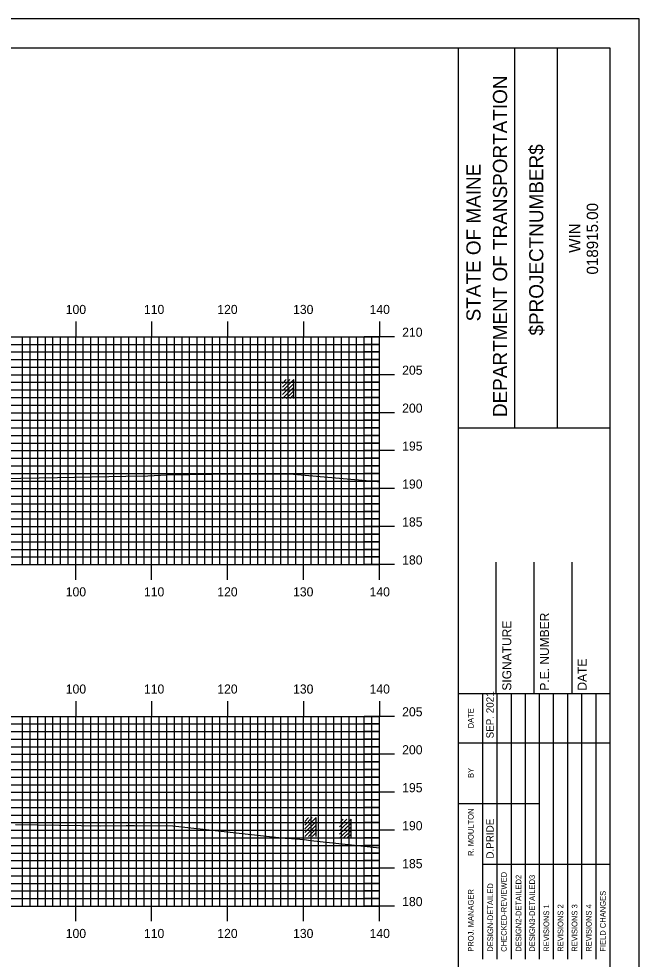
# Model space of a CAD drawing. Extents: x 851300 to 851643, y 366898 to 367118.
# Drawn here: x 851558 to 851639.7, y 366994.5 to 367118.4 of the extents above; entities that cross this region are included whole.
import ezdxf

# ---------------------------------------------------------------- set-up
doc = ezdxf.new("R2010")
doc.units = 0
for name, color, linetype in [('BORDER', 7, 'Continuous'), ('H_V ANNOTATION', 7, 'Continuous'), ('M_Buildings_Attachments', 7, 'Continuous'), ('M_Buildings_Rooftop', 7, 'Continuous'), ('MAJOR', 7, 'Continuous'), ('MINOR', 7, 'Continuous'), ('PLOT BOUNDARY', 7, 'Continuous'), ('S_Roadway_Centerline', 7, 'Continuous')]:
    doc.layers.add(name, color=color, linetype=linetype)

msp = doc.modelspace()

# ---------------------------------------------------------------- linework, layer by layer
at = {"layer": 'BORDER'}
for p, q in [((851615.9, 366904.47), (851615.9, 367114.47)), ((851623.36, 367064.47), (851623.36, 367114.47)), ((851628.95, 367064.47), (851628.95, 367114.47)), ((851615.91, 367064.46), (851635.9, 367064.46)), ((851620.9, 367029.48), (851620.9, 367046.77)), ((851625.9, 367029.48), (851625.9, 367046.77)), ((851630.9, 367029.48), (851630.9, 367046.77)), ((851615.9, 367029.48), (851635.9, 367029.48))]:
    msp.add_line(p, q, dxfattribs=at)
msp.add_lwpolyline([(851315.9, 366904.47), (851635.9, 366904.47), (851635.9, 367114.47), (851315.9, 367114.47)], close=True, dxfattribs=at)
for points in [[(851619.13, 367022.98), (851619.13, 367029.48)], [(851621, 366994.48), (851621, 367029.48)], [(851622.86, 367029.48), (851622.86, 366994.48)], [(851624.73, 366994.48), (851624.73, 367029.48)], [(851626.59, 366994.48), (851626.59, 367029.48)], [(851628.45, 366994.48), (851628.45, 367029.48)], [(851630.32, 366994.48), (851630.32, 367029.48)], [(851632.18, 366994.48), (851632.18, 367029.48)], [(851634.04, 366994.48), (851634.04, 367029.48)], [(851619.14, 366994.48), (851619.14, 367028.07)], [(851615.9, 367022.98), (851635.9, 367022.98)], [(851615.9, 367014.98), (851619.14, 367014.98)], [(851619.13, 367014.98), (851626.59, 367014.98)], [(851619.13, 367006.98), (851635.9, 367006.98)]]:
    msp.add_lwpolyline(points, dxfattribs=at)
at = {"layer": 'M_Buildings_Attachments'}
for p, q in [((851595.66, 367011.65), (851597.17, 367013.16)), ((851595.66, 367012.14), (851596.65, 367013.16)), ((851595.66, 367012.63), (851596.16, 367013.16)), ((851597.17, 367010.63), (851597.17, 367013.16)), ((851600.25, 367011.42), (851601.76, 367012.93)), ((851600.25, 367011.92), (851601.23, 367012.93)), ((851600.25, 367012.41), (851600.74, 367012.93)), ((851601.76, 367010.41), (851601.76, 367012.93)), ((851595.66, 367011.16), (851597.17, 367012.63)), ((851595.66, 367010.63), (851597.17, 367012.14)), ((851596.16, 367010.63), (851597.17, 367011.65)), ((851600.25, 367010.93), (851601.76, 367012.41)), ((851600.25, 367010.41), (851601.76, 367011.92)), ((851596.65, 367010.63), (851597.17, 367011.16)), ((851600.74, 367010.41), (851601.76, 367011.42)), ((851601.23, 367010.41), (851601.76, 367010.93))]:
    msp.add_line(p, q, dxfattribs=at)
at = {"layer": 'M_Buildings_Rooftop'}
for p, q in [((851592.72, 367069.34), (851594.23, 367070.85)), ((851592.72, 367069.83), (851593.71, 367070.85)), ((851592.72, 367070.33), (851593.22, 367070.85)), ((851592.72, 367068.85), (851594.23, 367070.33)), ((851592.72, 367068.32), (851594.23, 367069.83)), ((851594.23, 367068.32), (851594.23, 367070.85)), ((851593.22, 367068.32), (851594.23, 367069.34)), ((851593.71, 367068.32), (851594.23, 367068.85))]:
    msp.add_line(p, q, dxfattribs=at)
at = {"layer": 'MAJOR'}
for p, q in [((851565.5, 367078.48), (851565.5, 367076.47)), ((851575.5, 367078.48), (851575.5, 367076.47)), ((851585.5, 367078.48), (851585.5, 367076.47)), ((851595.5, 367078.48), (851595.5, 367076.47)), ((851605.5, 367078.48), (851605.5, 367076.47)), ((851325.5, 367076.47), (851605.5, 367076.47)), ((851325.5, 367076.47), (851605.5, 367076.47)), ((851565.5, 367046.47), (851565.5, 367076.47)), ((851575.5, 367046.47), (851575.5, 367076.47)), ((851585.5, 367046.47), (851585.5, 367076.47)), ((851595.5, 367046.47), (851595.5, 367076.47)), ((851607.51, 367076.47), (851603.5, 367076.47)), ((851605.5, 367046.47), (851605.5, 367076.47)), ((851605.5, 367046.47), (851605.5, 367076.47)), ((851325.5, 367071.47), (851605.5, 367071.47)), ((851607.51, 367071.47), (851603.5, 367071.47)), ((851325.5, 367066.47), (851605.5, 367066.47)), ((851607.51, 367066.47), (851603.5, 367066.47)), ((851325.5, 367061.47), (851605.5, 367061.47)), ((851607.51, 367061.47), (851603.5, 367061.47)), ((851325.5, 367056.47), (851605.5, 367056.47)), ((851607.51, 367056.47), (851603.5, 367056.47)), ((851325.5, 367051.47), (851605.5, 367051.47)), ((851607.51, 367051.47), (851603.5, 367051.47)), ((851325.5, 367046.47), (851605.5, 367046.47)), ((851325.5, 367046.47), (851605.5, 367046.47)), ((851565.5, 367044.47), (851565.5, 367046.47)), ((851575.5, 367044.47), (851575.5, 367046.47)), ((851585.5, 367044.47), (851585.5, 367046.47)), ((851595.5, 367044.47), (851595.5, 367046.47)), ((851607.51, 367046.47), (851603.5, 367046.47)), ((851605.5, 367044.47), (851605.5, 367046.47)), ((851565.5, 367028.48), (851565.5, 367026.47)), ((851575.5, 367028.48), (851575.5, 367026.47)), ((851585.5, 367028.48), (851585.5, 367026.47)), ((851595.5, 367028.48), (851595.5, 367026.47)), ((851605.5, 367028.48), (851605.5, 367026.47)), ((851325.5, 367026.47), (851605.5, 367026.47)), ((851325.5, 367026.47), (851605.5, 367026.47)), ((851565.5, 367001.47), (851565.5, 367026.47)), ((851575.5, 367001.47), (851575.5, 367026.47)), ((851585.5, 367001.47), (851585.5, 367026.47)), ((851595.5, 367001.47), (851595.5, 367026.47)), ((851607.51, 367026.47), (851603.5, 367026.47)), ((851605.5, 367001.47), (851605.5, 367026.47)), ((851605.5, 367001.47), (851605.5, 367026.47)), ((851325.5, 367021.47), (851605.5, 367021.47)), ((851607.51, 367021.47), (851603.5, 367021.47)), ((851325.5, 367016.47), (851605.5, 367016.47)), ((851607.51, 367016.47), (851603.5, 367016.47)), ((851325.5, 367011.47), (851605.5, 367011.47)), ((851607.51, 367011.47), (851603.5, 367011.47)), ((851325.5, 367006.47), (851605.5, 367006.47)), ((851607.51, 367006.47), (851603.5, 367006.47)), ((851325.5, 367001.47), (851605.5, 367001.47)), ((851325.5, 367001.47), (851605.5, 367001.47)), ((851565.5, 366999.47), (851565.5, 367001.47)), ((851575.5, 366999.47), (851575.5, 367001.47)), ((851585.5, 366999.47), (851585.5, 367001.47)), ((851595.5, 366999.47), (851595.5, 367001.47)), ((851607.51, 367001.47), (851603.5, 367001.47)), ((851605.5, 366999.47), (851605.5, 367001.47))]:
    msp.add_line(p, q, dxfattribs=at)
at = {"layer": 'MINOR'}
for p, q in [((851558.5, 367046.47), (851558.5, 367076.47)), ((851559.5, 367046.47), (851559.5, 367076.47)), ((851560.5, 367046.47), (851560.5, 367076.47)), ((851561.5, 367046.47), (851561.5, 367076.47)), ((851562.5, 367046.47), (851562.5, 367076.47)), ((851563.5, 367046.47), (851563.5, 367076.47)), ((851564.5, 367046.47), (851564.5, 367076.47)), ((851566.5, 367046.47), (851566.5, 367076.47)), ((851567.5, 367046.47), (851567.5, 367076.47)), ((851568.5, 367046.47), (851568.5, 367076.47)), ((851569.5, 367046.47), (851569.5, 367076.47)), ((851570.5, 367046.47), (851570.5, 367076.47)), ((851571.5, 367046.47), (851571.5, 367076.47)), ((851572.5, 367046.47), (851572.5, 367076.47)), ((851573.5, 367046.47), (851573.5, 367076.47)), ((851574.5, 367046.47), (851574.5, 367076.47)), ((851576.5, 367046.47), (851576.5, 367076.47)), ((851577.5, 367046.47), (851577.5, 367076.47)), ((851578.5, 367046.47), (851578.5, 367076.47)), ((851579.5, 367046.47), (851579.5, 367076.47)), ((851580.5, 367046.47), (851580.5, 367076.47)), ((851581.5, 367046.47), (851581.5, 367076.47)), ((851582.5, 367046.47), (851582.5, 367076.47)), ((851583.5, 367046.47), (851583.5, 367076.47)), ((851584.5, 367046.47), (851584.5, 367076.47)), ((851586.5, 367046.47), (851586.5, 367076.47)), ((851587.5, 367046.47), (851587.5, 367076.47)), ((851588.5, 367046.47), (851588.5, 367076.47)), ((851589.5, 367046.47), (851589.5, 367076.47)), ((851590.5, 367046.47), (851590.5, 367076.47)), ((851591.5, 367046.47), (851591.5, 367076.47)), ((851592.5, 367046.47), (851592.5, 367076.47)), ((851593.5, 367046.47), (851593.5, 367076.47)), ((851594.5, 367046.47), (851594.5, 367076.47)), ((851596.5, 367046.47), (851596.5, 367076.47)), ((851597.5, 367046.47), (851597.5, 367076.47)), ((851598.5, 367046.47), (851598.5, 367076.47)), ((851599.5, 367046.47), (851599.5, 367076.47)), ((851600.5, 367046.47), (851600.5, 367076.47)), ((851601.5, 367046.47), (851601.5, 367076.47)), ((851602.5, 367046.47), (851602.5, 367076.47)), ((851603.5, 367046.47), (851603.5, 367076.47)), ((851604.5, 367046.47), (851604.5, 367076.47)), ((851325.5, 367075.47), (851605.5, 367075.47)), ((851605.5, 367075.47), (851603.5, 367075.47)), ((851325.5, 367074.47), (851605.5, 367074.47)), ((851605.5, 367074.47), (851603.5, 367074.47)), ((851325.5, 367073.47), (851605.5, 367073.47)), ((851325.5, 367072.47), (851605.5, 367072.47)), ((851605.5, 367073.47), (851603.5, 367073.47)), ((851605.5, 367072.47), (851603.5, 367072.47)), ((851325.5, 367070.47), (851605.5, 367070.47)), ((851605.5, 367070.47), (851603.5, 367070.47)), ((851325.5, 367069.47), (851605.5, 367069.47)), ((851605.5, 367069.47), (851603.5, 367069.47)), ((851325.5, 367068.47), (851605.5, 367068.47)), ((851325.5, 367067.47), (851605.5, 367067.47)), ((851605.5, 367068.47), (851603.5, 367068.47)), ((851605.5, 367067.47), (851603.5, 367067.47)), ((851325.5, 367065.47), (851605.5, 367065.47)), ((851605.5, 367065.47), (851603.5, 367065.47)), ((851325.5, 367064.47), (851605.5, 367064.47)), ((851605.5, 367064.47), (851603.5, 367064.47)), ((851325.5, 367063.47), (851605.5, 367063.47)), ((851325.5, 367062.47), (851605.5, 367062.47)), ((851605.5, 367063.47), (851603.5, 367063.47)), ((851605.5, 367062.47), (851603.5, 367062.47)), ((851325.5, 367060.47), (851605.5, 367060.47)), ((851605.5, 367060.47), (851603.5, 367060.47)), ((851325.5, 367059.47), (851605.5, 367059.47)), ((851605.5, 367059.47), (851603.5, 367059.47)), ((851325.5, 367058.47), (851605.5, 367058.47)), ((851325.5, 367057.47), (851605.5, 367057.47)), ((851605.5, 367058.47), (851603.5, 367058.47)), ((851605.5, 367057.47), (851603.5, 367057.47)), ((851325.5, 367055.47), (851605.5, 367055.47)), ((851605.5, 367055.47), (851603.5, 367055.47)), ((851325.5, 367054.47), (851605.5, 367054.47)), ((851605.5, 367054.47), (851603.5, 367054.47)), ((851325.5, 367053.47), (851605.5, 367053.47)), ((851605.5, 367053.47), (851603.5, 367053.47)), ((851325.5, 367052.47), (851605.5, 367052.47)), ((851605.5, 367052.47), (851603.5, 367052.47)), ((851325.5, 367050.47), (851605.5, 367050.47)), ((851605.5, 367050.47), (851603.5, 367050.47)), ((851325.5, 367049.47), (851605.5, 367049.47)), ((851605.5, 367049.47), (851603.5, 367049.47)), ((851325.5, 367048.47), (851605.5, 367048.47)), ((851605.5, 367048.47), (851603.5, 367048.47)), ((851325.5, 367047.47), (851605.5, 367047.47)), ((851605.5, 367047.47), (851603.5, 367047.47)), ((851558.5, 367001.47), (851558.5, 367026.47)), ((851559.5, 367001.47), (851559.5, 367026.47)), ((851560.5, 367001.47), (851560.5, 367026.47)), ((851561.5, 367001.47), (851561.5, 367026.47)), ((851562.5, 367001.47), (851562.5, 367026.47)), ((851563.5, 367001.47), (851563.5, 367026.47)), ((851564.5, 367001.47), (851564.5, 367026.47)), ((851566.5, 367001.47), (851566.5, 367026.47)), ((851567.5, 367001.47), (851567.5, 367026.47)), ((851568.5, 367001.47), (851568.5, 367026.47)), ((851569.5, 367001.47), (851569.5, 367026.47)), ((851570.5, 367001.47), (851570.5, 367026.47)), ((851571.5, 367001.47), (851571.5, 367026.47)), ((851572.5, 367001.47), (851572.5, 367026.47)), ((851573.5, 367001.47), (851573.5, 367026.47)), ((851574.5, 367001.47), (851574.5, 367026.47)), ((851576.5, 367001.47), (851576.5, 367026.47)), ((851577.5, 367001.47), (851577.5, 367026.47)), ((851578.5, 367001.47), (851578.5, 367026.47)), ((851579.5, 367001.47), (851579.5, 367026.47)), ((851580.5, 367001.47), (851580.5, 367026.47)), ((851581.5, 367001.47), (851581.5, 367026.47)), ((851582.5, 367001.47), (851582.5, 367026.47)), ((851583.5, 367001.47), (851583.5, 367026.47)), ((851584.5, 367001.47), (851584.5, 367026.47)), ((851586.5, 367001.47), (851586.5, 367026.47)), ((851587.5, 367001.47), (851587.5, 367026.47)), ((851588.5, 367001.47), (851588.5, 367026.47)), ((851589.5, 367001.47), (851589.5, 367026.47)), ((851590.5, 367001.47), (851590.5, 367026.47)), ((851591.5, 367001.47), (851591.5, 367026.47)), ((851592.5, 367001.47), (851592.5, 367026.47)), ((851593.5, 367001.47), (851593.5, 367026.47)), ((851594.5, 367001.47), (851594.5, 367026.47)), ((851596.5, 367001.47), (851596.5, 367026.47)), ((851597.5, 367001.47), (851597.5, 367026.47)), ((851598.5, 367001.47), (851598.5, 367026.47)), ((851599.5, 367001.47), (851599.5, 367026.47)), ((851600.5, 367001.47), (851600.5, 367026.47)), ((851601.5, 367001.47), (851601.5, 367026.47)), ((851602.5, 367001.47), (851602.5, 367026.47)), ((851603.5, 367001.47), (851603.5, 367026.47)), ((851604.5, 367001.47), (851604.5, 367026.47)), ((851325.5, 367025.47), (851605.5, 367025.47)), ((851605.5, 367025.47), (851603.5, 367025.47)), ((851325.5, 367024.47), (851605.5, 367024.47)), ((851605.5, 367024.47), (851603.5, 367024.47)), ((851325.5, 367023.47), (851605.5, 367023.47)), ((851605.5, 367023.47), (851603.5, 367023.47)), ((851325.5, 367022.47), (851605.5, 367022.47)), ((851605.5, 367022.47), (851603.5, 367022.47)), ((851325.5, 367020.47), (851605.5, 367020.47)), ((851605.5, 367020.47), (851603.5, 367020.47)), ((851325.5, 367019.47), (851605.5, 367019.47)), ((851605.5, 367019.47), (851603.5, 367019.47)), ((851325.5, 367018.47), (851605.5, 367018.47)), ((851605.5, 367018.47), (851603.5, 367018.47)), ((851325.5, 367017.47), (851605.5, 367017.47)), ((851605.5, 367017.47), (851603.5, 367017.47)), ((851325.5, 367015.47), (851605.5, 367015.47)), ((851605.5, 367015.47), (851603.5, 367015.47)), ((851325.5, 367014.47), (851605.5, 367014.47)), ((851605.5, 367014.47), (851603.5, 367014.47)), ((851325.5, 367013.47), (851605.5, 367013.47)), ((851605.5, 367013.47), (851603.5, 367013.47)), ((851325.5, 367012.47), (851605.5, 367012.47)), ((851605.5, 367012.47), (851603.5, 367012.47)), ((851325.5, 367010.47), (851605.5, 367010.47)), ((851605.5, 367010.47), (851603.5, 367010.47)), ((851325.5, 367009.47), (851605.5, 367009.47)), ((851605.5, 367009.47), (851603.5, 367009.47)), ((851325.5, 367008.47), (851605.5, 367008.47)), ((851605.5, 367008.47), (851603.5, 367008.47)), ((851325.5, 367007.47), (851605.5, 367007.47)), ((851605.5, 367007.47), (851603.5, 367007.47)), ((851325.5, 367005.47), (851605.5, 367005.47)), ((851605.5, 367005.47), (851603.5, 367005.47)), ((851325.5, 367004.47), (851605.5, 367004.47)), ((851605.5, 367004.47), (851603.5, 367004.47)), ((851325.5, 367003.47), (851605.5, 367003.47)), ((851605.5, 367003.47), (851603.5, 367003.47)), ((851325.5, 367002.47), (851605.5, 367002.47)), ((851605.5, 367002.47), (851603.5, 367002.47))]:
    msp.add_line(p, q, dxfattribs=at)
at = {"layer": 'PLOT BOUNDARY'}
msp.add_lwpolyline([(851299.72, 366898.35), (851639.72, 366898.35), (851639.72, 367118.35), (851299.72, 367118.35)], close=True, dxfattribs=at)
at = {"layer": 'S_Roadway_Centerline'}
for points in [[(851555.87, 367057.79), (851563.08, 367057.93), (851572.09, 367058.12), (851575.02, 367058.17), (851577.51, 367058.27), (851586.54, 367058.42), (851591.01, 367058.41), (851593.71, 367058.43), (851605.25, 367057.4), (851605.5, 367057.41)], [(851557.55, 367012.21), (851566.2, 367012.1), (851568.77, 367012.07), (851572.16, 367012.08), (851573.24, 367012.09), (851578.31, 367012.04), (851591.83, 367010.56), (851593.07, 367010.44), (851593.36, 367010.41), (851595.58, 367010.23), (851596.48, 367010.13), (851605.5, 367009.16)]]:
    msp.add_lwpolyline(points, dxfattribs=at)

# ---------------------------------------------------------------- texts
at = {"layer": 'BORDER'}
for s, height, p in [('DEPARTMENT OF TRANSPORTATION', 1.8635, (851622.32, 367065.89)), ('$PROJECTNUMBER$', 1.8635, (851627.09, 367076.63)), ('STATE OF MAINE', 1.8635, (851618.82, 367078.5)), ('018915.00', 1.491, (851634.3, 367084.67)), ('WIN', 1.491, (851631.98, 367087.53)), ('SIGNATURE', 1.181, (851622.87, 367029.86)), ('P.E. NUMBER', 1.1811, (851627.83, 367029.86)), ('DATE', 1.181, (851632.79, 367029.86)), ('SEP. 2021', 0.969, (851620.55, 367023.57)), ('DATE', 0.743, (851617.91, 367024.89)), ('BY', 0.743, (851617.91, 367018.35)), ('R. MOULTON', 0.745, (851617.91, 367008.08)), ('D.PRIDE', 0.969, (851620.55, 367007.73)), ('CHECKED-REVIEWED', 0.7455, (851622.27, 366995.46)), ('DESIGN2-DETAILED2', 0.7455, (851624.2, 366995.46)), ('DESIGN3-DETAILED3', 0.7455, (851625.99, 366995.46)), ('DESIGN-DETAILED', 0.7455, (851620.48, 366995.46)), ('PROJ. MANAGER', 0.7455, (851617.91, 366995.46)), ('FIELD CHANGES', 0.7455, (851635.31, 366995.46)), ('REVISIONS 1', 0.7455, (851627.86, 366995.46)), ('REVISIONS 2', 0.7455, (851629.72, 366995.46)), ('REVISIONS 3', 0.7455, (851631.58, 366995.46)), ('REVISIONS 4', 0.7455, (851633.45, 366995.46))]:
    msp.add_text(s, height=height, rotation=90, dxfattribs=at).set_placement(p)
at = {"layer": 'H_V ANNOTATION'}
for s, p in [('100', (851564.19, 367079.47)), ('110', (851574.49, 367079.47)), ('120', (851584.15, 367079.47)), ('130', (851594.13, 367079.47)), ('140', (851604.21, 367079.47)), ('210', (851608.5, 367076.47)), ('205', (851608.5, 367071.47)), ('200', (851608.5, 367066.47)), ('195', (851608.5, 367061.47)), ('190', (851608.5, 367056.47)), ('185', (851608.5, 367051.47)), ('180', (851608.5, 367046.47)), ('100', (851564.19, 367042.27)), ('110', (851574.49, 367042.27)), ('120', (851584.15, 367042.27)), ('130', (851594.13, 367042.27)), ('140', (851604.21, 367042.27)), ('100', (851564.19, 367029.47)), ('110', (851574.49, 367029.47)), ('120', (851584.15, 367029.47)), ('130', (851594.13, 367029.47)), ('140', (851604.21, 367029.47)), ('205', (851608.5, 367026.47)), ('200', (851608.5, 367021.47)), ('195', (851608.5, 367016.47)), ('190', (851608.5, 367011.47)), ('185', (851608.5, 367006.47)), ('180', (851608.5, 367001.47)), ('100', (851564.19, 366997.27)), ('110', (851574.49, 366997.27)), ('120', (851584.15, 366997.27)), ('130', (851594.13, 366997.27)), ('140', (851604.21, 366997.27))]:
    msp.add_text(s, height=1.2, dxfattribs=at).set_placement(p)

doc.saveas('drawing.dxf')
